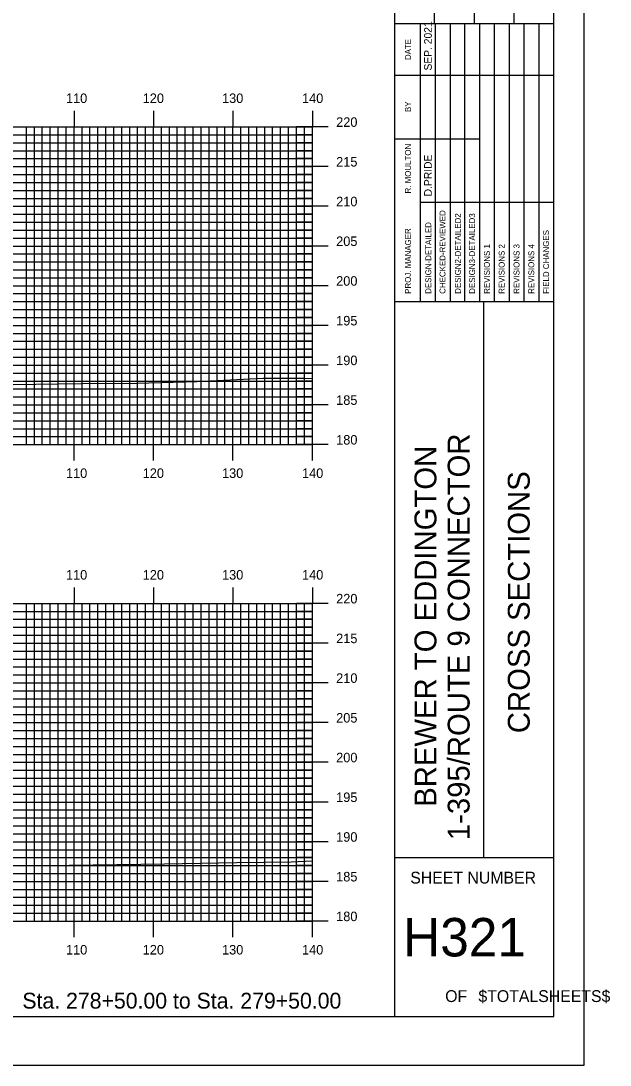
# Model space of a CAD drawing. Extents: x 1810587 to 1810930, y 442591 to 442811.
# Drawn here: x 1810855.7 to 1810929.9, y 442590.5 to 442722 of the extents above; entities that cross this region are included whole.
import ezdxf

# ---------------------------------------------------------------- set-up
doc = ezdxf.new("R2010")
doc.units = 0
for name, color, linetype in [('BORDER', 7, 'Continuous'), ('H_V ANNOTATION', 7, 'Continuous'), ('MAJOR', 7, 'Continuous'), ('MINOR', 7, 'Continuous'), ('PLOT BOUNDARY', 7, 'Continuous'), ('S_Roadway_Centerline', 7, 'Continuous')]:
    doc.layers.add(name, color=color, linetype=linetype)

msp = doc.modelspace()

# ---------------------------------------------------------------- linework, layer by layer
at = {"layer": 'BORDER'}
for p, q in [((1810902.78, 442596.67), (1810902.78, 442806.67)), ((1810907.78, 442721.67), (1810907.78, 442738.97)), ((1810912.78, 442721.67), (1810912.78, 442738.97)), ((1810917.78, 442721.67), (1810917.78, 442738.97)), ((1810902.78, 442721.67), (1810922.78, 442721.67)), ((1810902.78, 442686.67), (1810922.78, 442686.67)), ((1810913.96, 442616.67), (1810913.96, 442686.67)), ((1810902.78, 442616.67), (1810922.78, 442616.67))]:
    msp.add_line(p, q, dxfattribs=at)
msp.add_lwpolyline([(1810602.78, 442596.67), (1810922.78, 442596.67), (1810922.78, 442806.67), (1810602.78, 442806.67)], close=True, dxfattribs=at)
for points in [[(1810906.01, 442715.17), (1810906.01, 442721.67)], [(1810907.87, 442686.68), (1810907.87, 442721.67)], [(1810909.73, 442721.67), (1810909.73, 442686.68)], [(1810911.6, 442686.68), (1810911.6, 442721.67)], [(1810913.46, 442686.68), (1810913.46, 442721.67)], [(1810915.32, 442686.68), (1810915.32, 442721.67)], [(1810917.19, 442686.68), (1810917.19, 442721.67)], [(1810919.05, 442686.68), (1810919.05, 442721.67)], [(1810920.92, 442686.68), (1810920.92, 442721.67)], [(1810906.01, 442686.68), (1810906.01, 442720.26)], [(1810902.78, 442715.17), (1810922.78, 442715.17)], [(1810902.78, 442707.17), (1810906.01, 442707.17)], [(1810906.01, 442707.17), (1810913.46, 442707.17)], [(1810906.01, 442699.17), (1810922.78, 442699.17)]]:
    msp.add_lwpolyline(points, dxfattribs=at)
at = {"layer": 'MAJOR'}
for p, q in [((1810862.38, 442710.67), (1810862.38, 442708.67)), ((1810872.38, 442710.67), (1810872.38, 442708.67)), ((1810882.38, 442710.67), (1810882.38, 442708.67)), ((1810892.38, 442710.67), (1810892.38, 442708.67)), ((1810612.38, 442708.67), (1810892.38, 442708.67)), ((1810612.38, 442708.67), (1810892.38, 442708.67)), ((1810862.38, 442668.67), (1810862.38, 442708.67)), ((1810872.38, 442668.67), (1810872.38, 442708.67)), ((1810882.38, 442668.67), (1810882.38, 442708.67)), ((1810894.38, 442708.67), (1810890.37, 442708.67)), ((1810892.38, 442668.67), (1810892.38, 442708.67)), ((1810892.38, 442668.67), (1810892.38, 442708.67)), ((1810612.38, 442703.67), (1810892.38, 442703.67)), ((1810894.38, 442703.67), (1810890.37, 442703.67)), ((1810612.38, 442698.67), (1810892.38, 442698.67)), ((1810894.38, 442698.67), (1810890.37, 442698.67)), ((1810612.38, 442693.67), (1810892.38, 442693.67)), ((1810894.38, 442693.67), (1810890.37, 442693.67)), ((1810612.38, 442688.67), (1810892.38, 442688.67)), ((1810894.38, 442688.67), (1810890.37, 442688.67)), ((1810612.38, 442683.67), (1810892.38, 442683.67)), ((1810894.38, 442683.67), (1810890.37, 442683.67)), ((1810612.38, 442678.67), (1810892.38, 442678.67)), ((1810894.38, 442678.67), (1810890.37, 442678.67)), ((1810612.38, 442673.67), (1810892.38, 442673.67)), ((1810894.38, 442673.67), (1810890.37, 442673.67)), ((1810612.38, 442668.67), (1810892.38, 442668.67)), ((1810612.38, 442668.67), (1810892.38, 442668.67)), ((1810862.38, 442666.66), (1810862.38, 442668.67)), ((1810872.38, 442666.66), (1810872.38, 442668.67)), ((1810882.38, 442666.66), (1810882.38, 442668.67)), ((1810894.38, 442668.67), (1810890.37, 442668.67)), ((1810892.38, 442666.66), (1810892.38, 442668.67)), ((1810862.38, 442650.67), (1810862.38, 442648.67)), ((1810872.38, 442650.67), (1810872.38, 442648.67)), ((1810882.38, 442650.67), (1810882.38, 442648.67)), ((1810892.38, 442650.67), (1810892.38, 442648.67)), ((1810612.38, 442648.67), (1810892.38, 442648.67)), ((1810612.38, 442648.67), (1810892.38, 442648.67)), ((1810862.38, 442608.67), (1810862.38, 442648.67)), ((1810872.38, 442608.67), (1810872.38, 442648.67)), ((1810882.38, 442608.67), (1810882.38, 442648.67)), ((1810894.38, 442648.67), (1810890.37, 442648.67)), ((1810892.38, 442608.67), (1810892.38, 442648.67)), ((1810892.38, 442608.67), (1810892.38, 442648.67)), ((1810612.38, 442643.67), (1810892.38, 442643.67)), ((1810894.38, 442643.67), (1810890.37, 442643.67)), ((1810612.38, 442638.67), (1810892.38, 442638.67)), ((1810894.38, 442638.67), (1810890.37, 442638.67)), ((1810612.38, 442633.67), (1810892.38, 442633.67)), ((1810894.38, 442633.67), (1810890.37, 442633.67)), ((1810612.38, 442628.67), (1810892.38, 442628.67)), ((1810894.38, 442628.67), (1810890.37, 442628.67)), ((1810612.38, 442623.67), (1810892.38, 442623.67)), ((1810894.38, 442623.67), (1810890.37, 442623.67)), ((1810612.38, 442618.67), (1810892.38, 442618.67)), ((1810894.38, 442618.67), (1810890.37, 442618.67)), ((1810612.38, 442613.67), (1810892.38, 442613.67)), ((1810894.38, 442613.67), (1810890.37, 442613.67)), ((1810612.38, 442608.67), (1810892.38, 442608.67)), ((1810612.38, 442608.67), (1810892.38, 442608.67)), ((1810862.38, 442606.66), (1810862.38, 442608.67)), ((1810872.38, 442606.66), (1810872.38, 442608.67)), ((1810882.38, 442606.66), (1810882.38, 442608.67)), ((1810894.38, 442608.67), (1810890.37, 442608.67)), ((1810892.38, 442606.66), (1810892.38, 442608.67))]:
    msp.add_line(p, q, dxfattribs=at)
at = {"layer": 'MINOR'}
for p, q in [((1810856.38, 442668.67), (1810856.38, 442708.67)), ((1810857.38, 442668.67), (1810857.38, 442708.67)), ((1810858.38, 442668.67), (1810858.38, 442708.67)), ((1810859.38, 442668.67), (1810859.38, 442708.67)), ((1810860.38, 442668.67), (1810860.38, 442708.67)), ((1810861.38, 442668.67), (1810861.38, 442708.67)), ((1810863.38, 442668.67), (1810863.38, 442708.67)), ((1810864.38, 442668.67), (1810864.38, 442708.67)), ((1810865.38, 442668.67), (1810865.38, 442708.67)), ((1810866.38, 442668.67), (1810866.38, 442708.67)), ((1810867.38, 442668.67), (1810867.38, 442708.67)), ((1810868.38, 442668.67), (1810868.38, 442708.67)), ((1810869.38, 442668.67), (1810869.38, 442708.67)), ((1810870.38, 442668.67), (1810870.38, 442708.67)), ((1810871.38, 442668.67), (1810871.38, 442708.67)), ((1810873.38, 442668.67), (1810873.38, 442708.67)), ((1810874.38, 442668.67), (1810874.38, 442708.67)), ((1810875.38, 442668.67), (1810875.38, 442708.67)), ((1810876.38, 442668.67), (1810876.38, 442708.67)), ((1810877.38, 442668.67), (1810877.38, 442708.67)), ((1810878.38, 442668.67), (1810878.38, 442708.67)), ((1810879.38, 442668.67), (1810879.38, 442708.67)), ((1810880.38, 442668.67), (1810880.38, 442708.67)), ((1810881.38, 442668.67), (1810881.38, 442708.67)), ((1810883.38, 442668.67), (1810883.38, 442708.67)), ((1810884.38, 442668.67), (1810884.38, 442708.67)), ((1810885.38, 442668.67), (1810885.38, 442708.67)), ((1810886.38, 442668.67), (1810886.38, 442708.67)), ((1810887.38, 442668.67), (1810887.38, 442708.67)), ((1810888.38, 442668.67), (1810888.38, 442708.67)), ((1810889.38, 442668.67), (1810889.38, 442708.67)), ((1810890.38, 442668.67), (1810890.38, 442708.67)), ((1810891.38, 442668.67), (1810891.38, 442708.67)), ((1810612.38, 442707.67), (1810892.38, 442707.67)), ((1810892.38, 442707.67), (1810890.37, 442707.67)), ((1810612.38, 442706.67), (1810892.38, 442706.67)), ((1810612.38, 442705.67), (1810892.38, 442705.67)), ((1810892.38, 442706.67), (1810890.37, 442706.67)), ((1810892.38, 442705.67), (1810890.37, 442705.67)), ((1810612.38, 442704.67), (1810892.38, 442704.67)), ((1810892.38, 442704.67), (1810890.37, 442704.67)), ((1810612.38, 442702.67), (1810892.38, 442702.67)), ((1810612.38, 442701.67), (1810892.38, 442701.67)), ((1810892.38, 442702.67), (1810890.37, 442702.67)), ((1810892.38, 442701.67), (1810890.37, 442701.67)), ((1810612.38, 442700.67), (1810892.38, 442700.67)), ((1810892.38, 442700.67), (1810890.37, 442700.67)), ((1810612.38, 442699.67), (1810892.38, 442699.67)), ((1810892.38, 442699.67), (1810890.37, 442699.67)), ((1810612.38, 442697.67), (1810892.38, 442697.67)), ((1810892.38, 442697.67), (1810890.37, 442697.67)), ((1810612.38, 442696.67), (1810892.38, 442696.67)), ((1810892.38, 442696.67), (1810890.37, 442696.67)), ((1810612.38, 442695.67), (1810892.38, 442695.67)), ((1810892.38, 442695.67), (1810890.37, 442695.67)), ((1810612.38, 442694.67), (1810892.38, 442694.67)), ((1810892.38, 442694.67), (1810890.37, 442694.67)), ((1810612.38, 442692.67), (1810892.38, 442692.67)), ((1810892.38, 442692.67), (1810890.37, 442692.67)), ((1810612.38, 442691.67), (1810892.38, 442691.67)), ((1810892.38, 442691.67), (1810890.37, 442691.67)), ((1810612.38, 442690.67), (1810892.38, 442690.67)), ((1810892.38, 442690.67), (1810890.37, 442690.67)), ((1810612.38, 442689.67), (1810892.38, 442689.67)), ((1810892.38, 442689.67), (1810890.37, 442689.67)), ((1810612.38, 442687.67), (1810892.38, 442687.67)), ((1810892.38, 442687.67), (1810890.37, 442687.67)), ((1810612.38, 442686.67), (1810892.38, 442686.67)), ((1810892.38, 442686.67), (1810890.37, 442686.67)), ((1810612.38, 442685.67), (1810892.38, 442685.67)), ((1810612.38, 442684.67), (1810892.38, 442684.67)), ((1810892.38, 442685.67), (1810890.37, 442685.67)), ((1810892.38, 442684.67), (1810890.37, 442684.67)), ((1810612.38, 442682.67), (1810892.38, 442682.67)), ((1810892.38, 442682.67), (1810890.37, 442682.67)), ((1810612.38, 442681.67), (1810892.38, 442681.67)), ((1810612.38, 442680.67), (1810892.38, 442680.67)), ((1810892.38, 442681.67), (1810890.37, 442681.67)), ((1810892.38, 442680.67), (1810890.37, 442680.67)), ((1810612.38, 442679.67), (1810892.38, 442679.67)), ((1810892.38, 442679.67), (1810890.37, 442679.67)), ((1810612.38, 442677.67), (1810892.38, 442677.67)), ((1810612.38, 442676.67), (1810892.38, 442676.67)), ((1810892.38, 442677.67), (1810890.37, 442677.67)), ((1810892.38, 442676.67), (1810890.37, 442676.67)), ((1810612.38, 442675.67), (1810892.38, 442675.67)), ((1810892.38, 442675.67), (1810890.37, 442675.67)), ((1810612.38, 442674.67), (1810892.38, 442674.67)), ((1810892.38, 442674.67), (1810890.37, 442674.67)), ((1810612.38, 442672.67), (1810892.38, 442672.67)), ((1810892.38, 442672.67), (1810890.37, 442672.67)), ((1810612.38, 442671.67), (1810892.38, 442671.67)), ((1810892.38, 442671.67), (1810890.37, 442671.67)), ((1810612.38, 442670.67), (1810892.38, 442670.67)), ((1810892.38, 442670.67), (1810890.37, 442670.67)), ((1810612.38, 442669.67), (1810892.38, 442669.67)), ((1810892.38, 442669.67), (1810890.37, 442669.67)), ((1810612.38, 442647.67), (1810892.38, 442647.67)), ((1810856.38, 442608.67), (1810856.38, 442648.67)), ((1810857.38, 442608.67), (1810857.38, 442648.67)), ((1810858.38, 442608.67), (1810858.38, 442648.67)), ((1810859.38, 442608.67), (1810859.38, 442648.67)), ((1810860.38, 442608.67), (1810860.38, 442648.67)), ((1810861.38, 442608.67), (1810861.38, 442648.67)), ((1810863.38, 442608.67), (1810863.38, 442648.67)), ((1810864.38, 442608.67), (1810864.38, 442648.67)), ((1810865.38, 442608.67), (1810865.38, 442648.67)), ((1810866.38, 442608.67), (1810866.38, 442648.67)), ((1810867.38, 442608.67), (1810867.38, 442648.67)), ((1810868.38, 442608.67), (1810868.38, 442648.67)), ((1810869.38, 442608.67), (1810869.38, 442648.67)), ((1810870.38, 442608.67), (1810870.38, 442648.67)), ((1810871.38, 442608.67), (1810871.38, 442648.67)), ((1810873.38, 442608.67), (1810873.38, 442648.67)), ((1810874.38, 442608.67), (1810874.38, 442648.67)), ((1810875.38, 442608.67), (1810875.38, 442648.67)), ((1810876.38, 442608.67), (1810876.38, 442648.67)), ((1810877.38, 442608.67), (1810877.38, 442648.67)), ((1810878.38, 442608.67), (1810878.38, 442648.67)), ((1810879.38, 442608.67), (1810879.38, 442648.67)), ((1810880.38, 442608.67), (1810880.38, 442648.67)), ((1810881.38, 442608.67), (1810881.38, 442648.67)), ((1810883.38, 442608.67), (1810883.38, 442648.67)), ((1810884.38, 442608.67), (1810884.38, 442648.67)), ((1810885.38, 442608.67), (1810885.38, 442648.67)), ((1810886.38, 442608.67), (1810886.38, 442648.67)), ((1810887.38, 442608.67), (1810887.38, 442648.67)), ((1810888.38, 442608.67), (1810888.38, 442648.67)), ((1810889.38, 442608.67), (1810889.38, 442648.67)), ((1810892.38, 442647.67), (1810890.37, 442647.67)), ((1810890.38, 442608.67), (1810890.38, 442648.67)), ((1810891.38, 442608.67), (1810891.38, 442648.67)), ((1810612.38, 442646.67), (1810892.38, 442646.67)), ((1810892.38, 442646.67), (1810890.37, 442646.67)), ((1810612.38, 442645.67), (1810892.38, 442645.67)), ((1810892.38, 442645.67), (1810890.37, 442645.67)), ((1810612.38, 442644.67), (1810892.38, 442644.67)), ((1810892.38, 442644.67), (1810890.37, 442644.67)), ((1810612.38, 442642.67), (1810892.38, 442642.67)), ((1810892.38, 442642.67), (1810890.37, 442642.67)), ((1810612.38, 442641.67), (1810892.38, 442641.67)), ((1810892.38, 442641.67), (1810890.37, 442641.67)), ((1810612.38, 442640.67), (1810892.38, 442640.67)), ((1810892.38, 442640.67), (1810890.37, 442640.67)), ((1810612.38, 442639.67), (1810892.38, 442639.67)), ((1810892.38, 442639.67), (1810890.37, 442639.67)), ((1810612.38, 442637.67), (1810892.38, 442637.67)), ((1810892.38, 442637.67), (1810890.37, 442637.67)), ((1810612.38, 442636.67), (1810892.38, 442636.67)), ((1810892.38, 442636.67), (1810890.37, 442636.67)), ((1810612.38, 442635.67), (1810892.38, 442635.67)), ((1810612.38, 442634.67), (1810892.38, 442634.67)), ((1810892.38, 442635.67), (1810890.37, 442635.67)), ((1810892.38, 442634.67), (1810890.37, 442634.67)), ((1810612.38, 442632.67), (1810892.38, 442632.67)), ((1810892.38, 442632.67), (1810890.37, 442632.67)), ((1810612.38, 442631.67), (1810892.38, 442631.67)), ((1810612.38, 442630.67), (1810892.38, 442630.67)), ((1810892.38, 442631.67), (1810890.37, 442631.67)), ((1810892.38, 442630.67), (1810890.37, 442630.67)), ((1810612.38, 442629.67), (1810892.38, 442629.67)), ((1810892.38, 442629.67), (1810890.37, 442629.67)), ((1810612.38, 442627.67), (1810892.38, 442627.67)), ((1810612.38, 442626.67), (1810892.38, 442626.67)), ((1810892.38, 442627.67), (1810890.37, 442627.67)), ((1810892.38, 442626.67), (1810890.37, 442626.67)), ((1810612.38, 442625.67), (1810892.38, 442625.67)), ((1810892.38, 442625.67), (1810890.37, 442625.67)), ((1810612.38, 442624.67), (1810892.38, 442624.67)), ((1810892.38, 442624.67), (1810890.37, 442624.67)), ((1810612.38, 442622.67), (1810892.38, 442622.67)), ((1810892.38, 442622.67), (1810890.37, 442622.67)), ((1810612.38, 442621.67), (1810892.38, 442621.67)), ((1810892.38, 442621.67), (1810890.37, 442621.67)), ((1810612.38, 442620.67), (1810892.38, 442620.67)), ((1810892.38, 442620.67), (1810890.37, 442620.67)), ((1810612.38, 442619.67), (1810892.38, 442619.67)), ((1810892.38, 442619.67), (1810890.37, 442619.67)), ((1810612.38, 442617.67), (1810892.38, 442617.67)), ((1810892.38, 442617.67), (1810890.37, 442617.67)), ((1810612.38, 442616.67), (1810892.38, 442616.67)), ((1810892.38, 442616.67), (1810890.37, 442616.67)), ((1810612.38, 442615.67), (1810892.38, 442615.67)), ((1810892.38, 442615.67), (1810890.37, 442615.67)), ((1810612.38, 442614.67), (1810892.38, 442614.67)), ((1810892.38, 442614.67), (1810890.37, 442614.67)), ((1810612.38, 442612.67), (1810892.38, 442612.67)), ((1810892.38, 442612.67), (1810890.37, 442612.67)), ((1810612.38, 442611.67), (1810892.38, 442611.67)), ((1810892.38, 442611.67), (1810890.37, 442611.67)), ((1810612.38, 442610.67), (1810892.38, 442610.67)), ((1810612.38, 442609.67), (1810892.38, 442609.67)), ((1810892.38, 442610.67), (1810890.37, 442610.67)), ((1810892.38, 442609.67), (1810890.37, 442609.67))]:
    msp.add_line(p, q, dxfattribs=at)
at = {"layer": 'PLOT BOUNDARY'}
msp.add_lwpolyline([(1810586.59, 442590.55), (1810926.59, 442590.55), (1810926.59, 442810.55), (1810586.59, 442810.55)], close=True, dxfattribs=at)
at = {"layer": 'S_Roadway_Centerline'}
for points in [[(1810773.84, 442677.41), (1810786.87, 442677.39), (1810792.95, 442677.14), (1810799.06, 442677.04), (1810807.83, 442676.89), (1810816.29, 442677.09), (1810825.96, 442676.77), (1810827.68, 442676.77), (1810835.99, 442676.51), (1810848.92, 442676.2), (1810851.83, 442676.2), (1810863.27, 442676.36), (1810870.27, 442676.41), (1810877.89, 442676.63), (1810886.2, 442677.02), (1810891.25, 442677.01), (1810892.38, 442677)], [(1810772.76, 442616.06), (1810781.61, 442616.48), (1810785.29, 442616.7), (1810806.8, 442615.83), (1810808.92, 442615.77), (1810810.42, 442615.87), (1810825.7, 442615.72), (1810833.52, 442615.71), (1810834.39, 442615.74), (1810853.03, 442615.66), (1810855.83, 442615.63), (1810858.8, 442615.66), (1810873.76, 442615.88), (1810882.83, 442616.05), (1810889.73, 442616.13), (1810892.38, 442616.25)]]:
    msp.add_lwpolyline(points, dxfattribs=at)

# ---------------------------------------------------------------- texts
at = {"layer": 'BORDER'}
for s, height, p in [('SEP. 2021', 0.969, (1810907.42, 442715.76)), ('DATE', 0.743, (1810904.79, 442717.08)), ('BY', 0.743, (1810904.79, 442710.54)), ('R. MOULTON', 0.745, (1810904.79, 442700.28)), ('D.PRIDE', 0.969, (1810907.42, 442699.92)), ('CHECKED-REVIEWED', 0.7455, (1810909.14, 442687.65)), ('DESIGN2-DETAILED2', 0.7455, (1810911.08, 442687.65)), ('DESIGN3-DETAILED3', 0.7455, (1810912.87, 442687.65)), ('DESIGN-DETAILED', 0.7455, (1810907.35, 442687.65)), ('PROJ. MANAGER', 0.7455, (1810904.79, 442687.65)), ('FIELD CHANGES', 0.7455, (1810922.18, 442687.65)), ('REVISIONS 1', 0.7455, (1810914.73, 442687.65)), ('REVISIONS 2', 0.7455, (1810916.59, 442687.65)), ('REVISIONS 3', 0.7455, (1810918.46, 442687.65)), ('REVISIONS 4', 0.7455, (1810920.32, 442687.65)), ('1-395/ROUTE 9 CONNECTOR', 2.7557, (1810912.18, 442618.87)), ('BREWER TO EDDINGTON', 2.7557, (1810908, 442623.07)), ('CROSS SECTIONS', 2.7557, (1810919.75, 442632.34))]:
    msp.add_text(s, height=height, rotation=90, dxfattribs=at).set_placement(p)
for s, height, p in [('SHEET NUMBER', 1.4905, (1810904.71, 442613.4)), ('H321', 4.839, (1810903.81, 442604.23)), ('OF', 1.491, (1810909.11, 442598.49)), ('$TOTALSHEETS$', 1.4905, (1810913.29, 442598.49))]:
    msp.add_text(s, height=height, dxfattribs=at).set_placement(p)
at = {"layer": 'H_V ANNOTATION'}
for s, height, p in [('110', 1.2, (1810861.36, 442711.67)), ('120', 1.2, (1810871.02, 442711.67)), ('130', 1.2, (1810881.01, 442711.67)), ('140', 1.2, (1810891.08, 442711.67)), ('220', 1.2, (1810895.38, 442708.67)), ('215', 1.2, (1810895.38, 442703.67)), ('210', 1.2, (1810895.38, 442698.67)), ('205', 1.2, (1810895.38, 442693.67)), ('200', 1.2, (1810895.38, 442688.67)), ('195', 1.2, (1810895.38, 442683.67)), ('190', 1.2, (1810895.38, 442678.67)), ('185', 1.2, (1810895.38, 442673.67)), ('180', 1.2, (1810895.38, 442668.67)), ('110', 1.2, (1810861.36, 442664.47)), ('120', 1.2, (1810871.02, 442664.47)), ('130', 1.2, (1810881.01, 442664.47)), ('140', 1.2, (1810891.08, 442664.47)), ('110', 1.2, (1810861.36, 442651.67)), ('120', 1.2, (1810871.02, 442651.67)), ('130', 1.2, (1810881.01, 442651.67)), ('140', 1.2, (1810891.08, 442651.67)), ('220', 1.2, (1810895.38, 442648.67)), ('215', 1.2, (1810895.38, 442643.67)), ('210', 1.2, (1810895.38, 442638.67)), ('205', 1.2, (1810895.38, 442633.67)), ('200', 1.2, (1810895.38, 442628.67)), ('195', 1.2, (1810895.38, 442623.67)), ('190', 1.2, (1810895.38, 442618.67)), ('185', 1.2, (1810895.38, 442613.67)), ('180', 1.2, (1810895.38, 442608.67)), ('110', 1.2, (1810861.36, 442604.47)), ('120', 1.2, (1810871.02, 442604.47)), ('130', 1.2, (1810881.01, 442604.47)), ('140', 1.2, (1810891.08, 442604.47)), ('Sta. 278+50.00 to Sta. 279+50.00', 2.0004, (1810855.87, 442597.66))]:
    msp.add_text(s, height=height, dxfattribs=at).set_placement(p)

doc.saveas('drawing.dxf')
